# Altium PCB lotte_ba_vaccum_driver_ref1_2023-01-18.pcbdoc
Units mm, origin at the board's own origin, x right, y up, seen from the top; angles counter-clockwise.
Board outline 98.93 x 65.02 mm, 2 copper layers (Top Layer, Bottom Layer); 20 components, 26 nets, 68 pads, 10 vias.
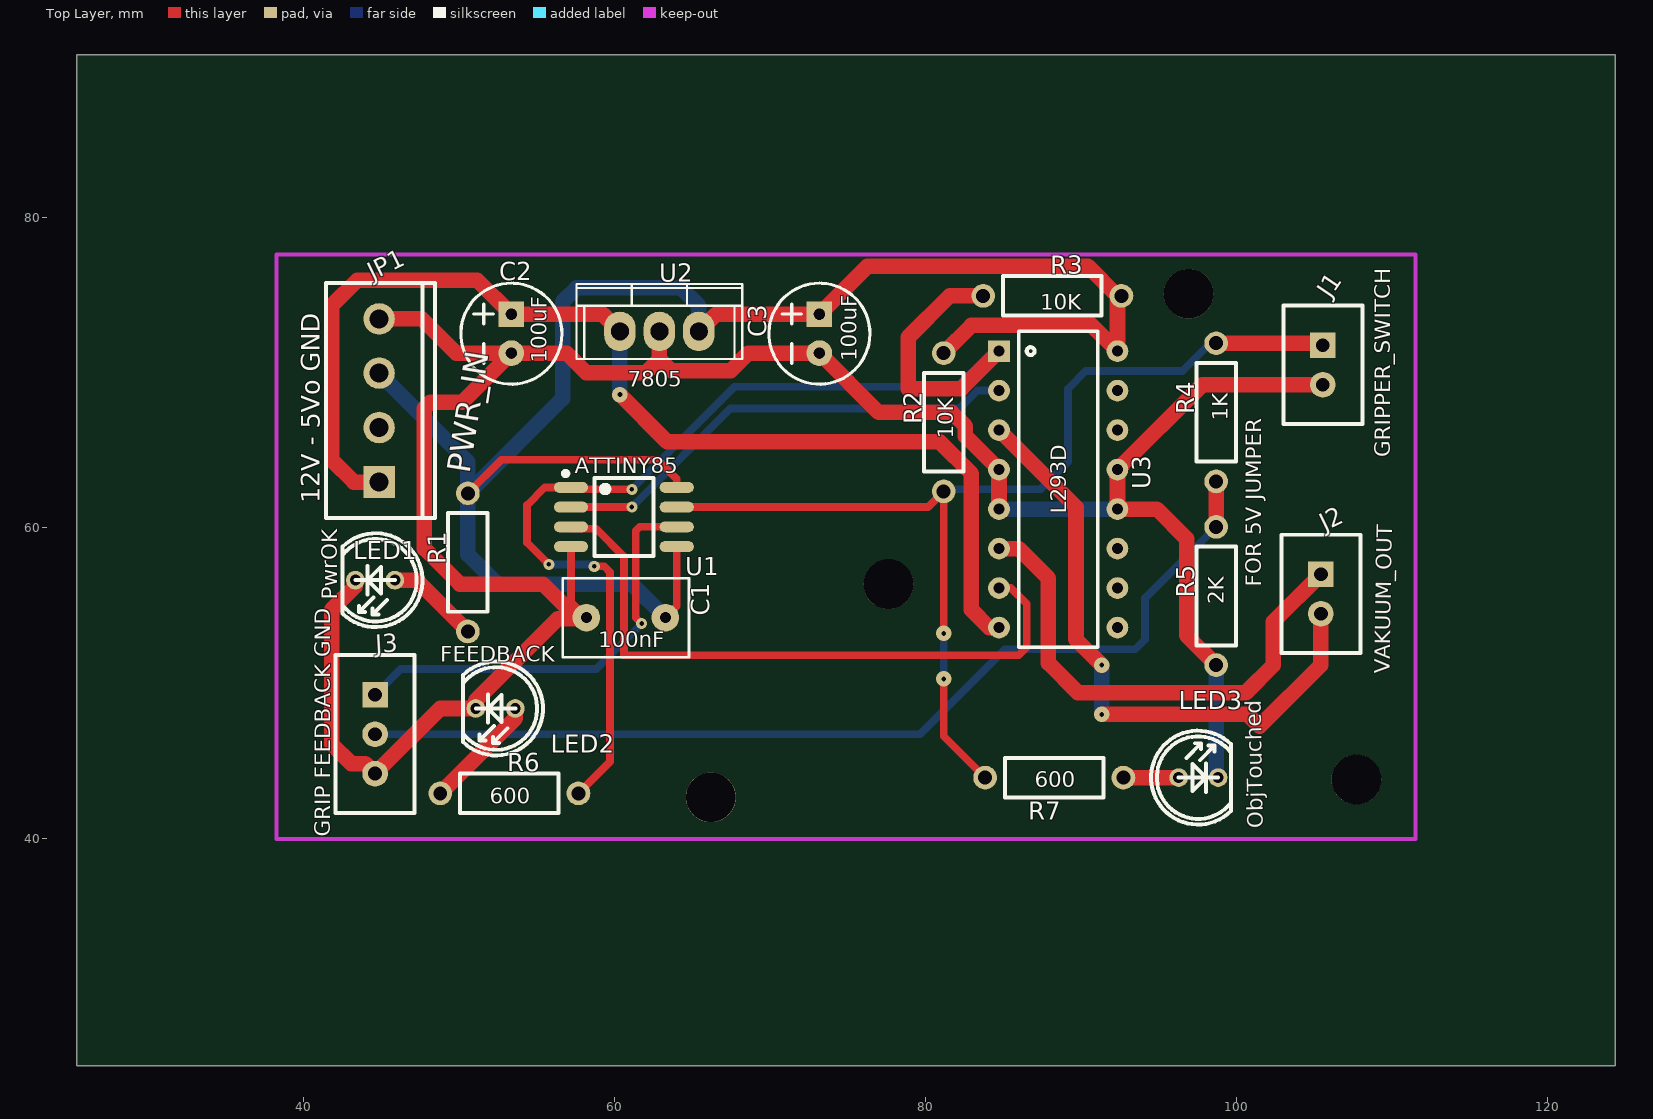
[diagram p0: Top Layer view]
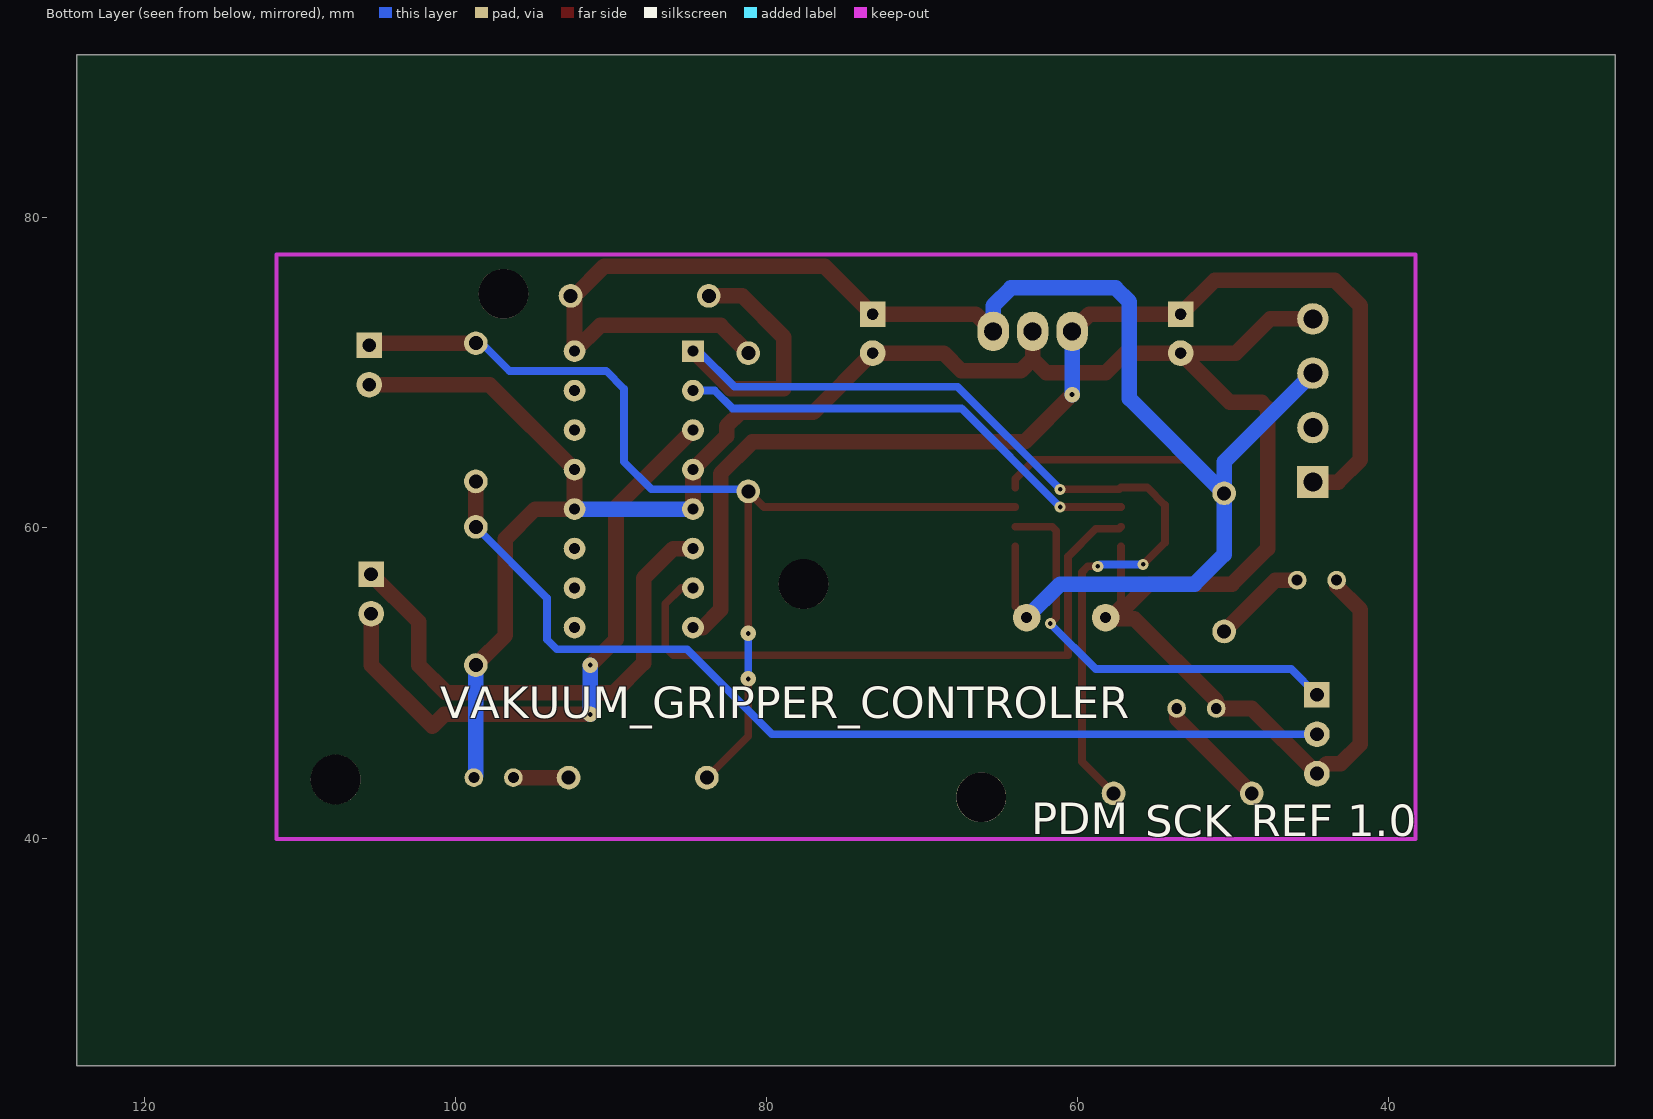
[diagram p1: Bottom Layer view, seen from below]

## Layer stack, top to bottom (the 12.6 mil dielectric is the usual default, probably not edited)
Top Layer: signal copper (thickness not stored)
Dielectric: dielectric 0.32, FR-4, Dk 4.8
Bottom Layer: signal copper (thickness not stored)

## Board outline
124.333,25.4 25.4,25.4 25.4,90.424 124.333,90.424

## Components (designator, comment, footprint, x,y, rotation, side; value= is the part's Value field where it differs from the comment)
C1 "100nF" RAD-0.2 58.166,54.229 r270 top
C2 "100UF-POLAR-RADIAL-2.5MM-25V-20%" CPOL-RADIAL-2.5MM-6.5MM 53.34,71.247 r90 top
C3 "100UF-POLAR-RADIAL-2.5MM-25V-20%" CPOL-RADIAL-2.5MM-6.5MM 73.152,71.247 r90 top
J1 "JST-2" JST-2 105.537,69.215 r0 top
J2 "JST-2" JST-2 105.41,54.483 r0 top
J3 "JST-3" JST-3 44.577,46.736 r0 top
JP1 "M04" SCREWTERMINAL-3.5MM-4 44.831,68.199 r90 top
LED1 "5mm Red LED THT (C87271)" LED-5MM-2.54MM 44.577,56.642 r180 top
LED2 "5mm Red LED THT (C87271)" LED-5MM-2.54MM 52.324,48.387 r180 top
LED3 "5mm Red LED THT (C87271)" LED-5MM-2.54MM 97.536,43.942 r0 top
R1 "RESISTOR 1/4" "AXIAL 1/4" 50.546,58.42 r90 top
R2 "RESISTOR 1/4" "AXIAL 1/4" 81.153,67.437 r90 top
R3 "RESISTOR 1/4" "AXIAL 1/4" 88.773,74.93 r0 top
R4 "RESISTOR 1/4" "AXIAL 1/4" 98.679,68.072 r90 top
R5 "RESISTOR 1/4" "AXIAL 1/4" 98.679,56.261 r90 top
R6 "RESISTOR 1/4" "AXIAL 1/4" 53.848,42.926 r0 top
R7 "RESISTOR 1/4" "AXIAL 1/4" 87.63,43.942 r180 top
U1 "ATTINY85V-10SU" SOIC-8_208MIL 60.579,60.706 r0 top
U2 "7805" TO-220 62.865,72.644 r0 top
U3 "L293D" DIP16 88.519,62.484 r270 top

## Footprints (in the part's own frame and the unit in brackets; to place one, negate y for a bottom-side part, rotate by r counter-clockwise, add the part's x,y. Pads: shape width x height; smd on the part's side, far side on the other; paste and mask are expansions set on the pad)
"AXIAL 1/4" [mil]
  round 60 hole 35.4: 1(-200,0) 2(150,0)
  silkscreen extent -150,-50 100,50
CPOL-RADIAL-2.5MM-6.5MM [mil]
  rect 65x65 hole 27.56 slot 27.76 at 0 deg: 1(98.42,0)
  round 65 hole 27.56 slot 27.76 at 0 deg: 2(0,0)
  silkscreen extent -79,-128 177,128
DIP16 [mil]
  rect 55x55 hole 28: 1(-350,-150)
  round 55 hole 28: 2(-250,-150) 3(-150,-150) 4(-50,-150) 5(50,-150) 6(150,-150) 7(250,-150) 8(350,-150) 9(350,150) 10(250,150) 11(150,150) 12(50,150) 13(-50,150) 14(-150,150) 15(-250,150) 16(-350,150)
  silkscreen extent -400,-100 400,100
JST-2 [mil]
  rect 65x65 hole 35: 1(0,100)
  round 65 hole 35: 2(0,0)
  silkscreen extent -100,-100 100,200
JST-3 [mil]
  rect 65x65 hole 35: 1(0,100)
  round 65 hole 35: 2(0,0) 3(0,-100)
  silkscreen extent -100,-200 100,200
LED-5MM-2.54MM [mm]
  round 1.2 hole 0.7: 1(-1.27,0) 2(1.27,0)
  silkscreen extent -3.04,-3.02 2.08,3.02
RAD-0.2 [mil]
  round 70 hole 28: 1(0,200) 2(0,0)
  silkscreen extent -100,-60 100,260
SCREWTERMINAL-3.5MM-4 [mil]
  rect 80x80 hole 47.2: 1(-206.5,0)
  round 80 hole 47.2: 2(-68.5,0) 3(69.5,0) 4(206.5,0)
  silkscreen extent -298,-142 298,134
SOIC-8_208MIL [mm]
  oval 2.2x0.7 smd: 1(-3.4,1.905) 2(-3.4,0.635) 3(-3.4,-0.635) 4(-3.4,-1.905) 5(3.4,-1.905) 6(3.4,-0.635) 7(3.4,0.635) 8(3.4,1.905)
  silkscreen extent -3.9,-2.5 1.9,2.95
TO-220 [mil]
  oval 80x100 hole 45 slot 45.2 at 90 deg: 1(-100,0) 2(0,0) 3(100,0)
  silkscreen extent -210,-70 210,120

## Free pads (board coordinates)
  round 3.2 hole 3.2 unplated: ""(66.167,42.672) ""(77.597,56.388) ""(96.901,75.057) ""(107.696,43.815)

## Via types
v1: diameter 1, hole 0.305, Top Layer to Bottom Layer, tented both sides, 5 vias
v2: diameter 0.71, hole 0.305, Top Layer to Bottom Layer, tented both sides, 5 vias

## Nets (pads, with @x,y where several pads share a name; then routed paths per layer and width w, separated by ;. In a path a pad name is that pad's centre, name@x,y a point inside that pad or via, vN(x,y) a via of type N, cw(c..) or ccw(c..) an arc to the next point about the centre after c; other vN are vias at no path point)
+5V: C1.1 C3.1 JP1.3 R1.2 R2.2 R3.2 U1.5 U1.8 U2.3 U3.16 | length 120.7
  Top Layer w0.5: R1.2 52.705,64.389 62.738,64.389 63.979,63.148 U1.8 ; C1.1 63.979,54.962 U1.5
  Top Layer w1: U2.3 66.508,73.747 C3.1 76.24,76.835 90.424,76.835 92.329,74.93 R3.2 92.329,74.676 U3.16 90.678,73.025 83.312,73.025 82.931,73.025 R2.2
  Bottom Layer w1: JP1.3 50.546,64.249 R1.2 ; C1.1 61.087,56.388 52.451,56.388 50.546,58.293 R1.2 ; U2.3 65.405,74.295 64.262,75.438 57.531,75.438 56.642,74.549 56.642,68.326 R1.2
GND: C1.2 C2.2 C3.2 J1.2 J3.3 JP1.4 LED1.2 LED2.2 LED3.2 R5.1 U1.4 U2.2 U3.4 U3.5 U3.12 U3.13 | length 163.4
  Top Layer w0.5: U1.4 57.179,55.216 C1.2
  Top Layer w1: LED1.2 43.307,56.261 41.783,54.737 41.783,46.101 43.053,44.831 43.942,44.831 J3.3 48.768,48.387 LED2.2 51.054,48.895 56.321,54.153 58.099,54.153 C1.2 57.531,54.229 55.372,56.388 50.038,56.388 47.752,58.674 47.752,67.691 48.133,68.072 50.165,68.072 C2.2 ; JP1.4 47.587,73.444 49.784,71.247 C2.2 ; U2.2 62.865,70.866 ; U3.5 U3.4 82.55,65.913 82.55,66.548 81.661,67.437 76.962,67.437 C3.2 68.58,71.247 67.437,70.104 63.627,70.104 62.865,70.866 ; R5.1 96.774,53.086 96.774,59.309 94.869,61.214 U3.12 U3.13 97.79,69.215 J1.2 ; C2.2 56.896,71.247 58.166,69.977 61.976,69.977 62.865,70.866
  Bottom Layer w1: U3.5 U3.12 ; R5.1 98.679,44.069 LED3.2
J3_2: J3.2 R4.1 R5.2 | length 64.1
  Top Layer w1: R5.2 R4.1
  Bottom Layer w0.5: J3.2 79.629,46.736 85.09,52.197 93.472,52.197 94.107,52.832 94.107,55.499 R5.2
JP1_2: JP1.2
LED1_1: LED1.1 R1.1 | length 6.1
  Top Layer w1: LED1.1 47.244,56.642 R1.1
R6_1: LED2.1 R6.1 | length 7.5
  Top Layer w1: R6.1 53.594,47.752 LED2.1
R7_1: LED3.1 R7.1 | length 3.6
  Top Layer w1: R7.1 LED3.1
S$15: 
S$18: 
S$20: 
S$22: 
S$24: 
S$26: 
U1_1: R3.1 R6.2 U1.1 U3.1 | length 74.2
  Top Layer w0.5: v2(55.753,57.658) 54.356,59.055 54.356,61.468 55.499,62.611 U1.1 57.306,62.484 v2(61.087,62.484) ; R6.2 59.69,44.958 59.69,57.15 59.309,57.531 v2(58.674,57.531)
  Top Layer w1: R3.1 81.534,74.93 78.867,72.263 78.867,68.961 82.296,68.961 U3.1
  Bottom Layer w0.5: v2(55.753,57.658) 58.547,57.658 v2(58.674,57.531) ; v2(61.087,62.484) 67.691,69.088 82.042,69.088 84.328,71.374 U3.1
U1_2: U1.2 U3.2 | length 30.6
  Top Layer w0.5: U1.2 v2(61.087,61.341)
  Bottom Layer w0.5: v2(61.087,61.341) 67.437,67.691 82.169,67.691 83.312,68.834 U3.2
U1_3: U1.3 U3.7 | length 41.7
  Top Layer w0.5: U1.3 57.305,59.944 58.801,59.944 60.579,58.166 60.579,51.816 85.979,51.816 86.487,52.324 86.487,55.118 85.471,56.134 U3.7
U1_6: J3.1 U1.6 | length 27.9
  Top Layer w0.5: v2(61.722,53.848) 61.341,54.229 61.341,59.817 61.595,60.071 U1.6
  Bottom Layer w0.5: J3.1 46.228,50.927 58.801,50.927 v2(61.722,53.848)
U1_7: J1.1 R2.1 R4.2 R7.2 U1.7 | length 68.2
  Top Layer w0.5: U1.7 80.137,61.341 R2.1 v1(81.153,53.213) ; v1(81.153,50.292) 81.153,46.609 R7.2
  Top Layer w1: R4.2 105.41,71.882 J1.1
  Bottom Layer w0.5: v1(81.153,50.292) v1(81.153,53.213) ; R2.1 81.28,62.484 87.376,62.484 89.154,64.262 89.154,68.961 90.297,70.104 96.52,70.104 98.298,71.882 R4.2
U3_3: J2.2 U3.3 | length 49.2
  Top Layer w1: U3.3 89.662,61.341 89.662,52.832 v1(91.313,51.181) ; v1(91.313,48.006) 100.711,48.006 101.473,47.244 ; 101.473,47.244 105.41,51.181 ; 101.473,47.244 105.41,51.181 ; 105.41,51.181 J2.2 105.41,51.181
  Bottom Layer w1: v1(91.313,48.006) v1(91.313,51.181)
U3_6: J2.1 U3.6 | length 32.5
  Top Layer w1: U3.6 85.979,58.674 87.884,56.769 87.884,51.308 89.789,49.403 100.584,49.403 102.362,51.181 102.362,53.975 J2.1
U3_9: U3.9
U3_10: U3.10
U3_11: U3.11
U3_14: U3.14
U3_15: U3.15
VCC: C2.1 JP1.1 U2.1 U3.8 | length 73.9
  Top Layer w1: JP1.1 43.218,62.954 41.783,64.389 41.783,74.295 43.434,75.946 51.141,75.946 C2.1 59.222,73.747 U2.1 ; v1(60.325,68.58) 63.373,65.532 80.899,65.532 82.931,63.5 82.931,54.737 84.074,53.594 U3.8
  Bottom Layer w1: v1(60.325,68.58) U2.1

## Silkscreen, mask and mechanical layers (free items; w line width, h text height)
Top Overlay:
  text "10K" at 87.376,74.049 h1
  text "100uF" at 75.557,70.739 h1 r90
  text "100uF" at 55.618,70.612 h1 r90
  text "7805" at 60.833,69.096 h1
  text "1K" at 99.433,66.891 h1 r90
  text "10K" at 81.78,65.748 h1 r90
  text "GRIPPER_SWITCH" at 109.885,64.544 h1 r90
  text "ATTINY85" at 57.404,63.508 h1
  text "PWR_IN" at 50.652,63.454 h1.5 r81
  text "12V - 5Vo GND" at 41.006,61.587 h1.2 r90
  text "L293D" at 89.019,60.922 h1 r90
  text "FOR 5V JUMPER" at 101.592,56.223 h1 r90
  text "PwrOK" at 42.156,55.372 h1 r90
  text "2K" at 99.179,55.08 h1 r90
  text "100nF" at 58.928,52.332 h1
  text "FEEDBACK" at 48.768,51.405 h1
  text "VAKUUM_OUT" at 109.847,50.626 h1 r89
  text "600" at 86.995,43.315 h1
  text "600" at 51.943,42.261 h1
  text "ObjTouched" at 101.719,40.692 h1 r91
  text "GRIP FEEDBACK GND" at 41.686,40.137 h1 r90
Bottom Overlay:
  text "VAKUUM_GRIPPER_CONTROLER" at 100.965,47.752 h2.03
  text "PDM" at 62.941,40.294 h2.03
  text "REF 1.0" at 48.84,40.167 h2.03
  text "SCK" at 55.626,40.132 h2.03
